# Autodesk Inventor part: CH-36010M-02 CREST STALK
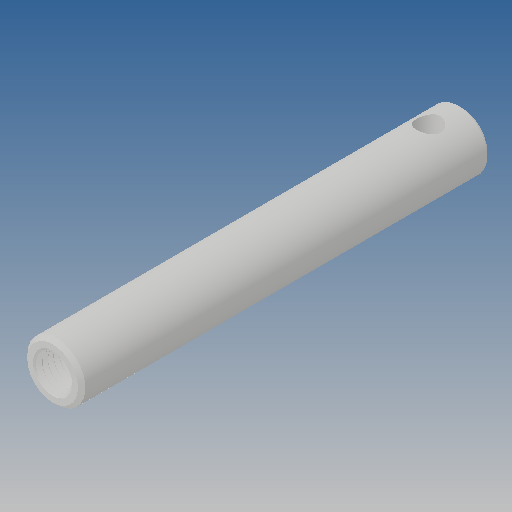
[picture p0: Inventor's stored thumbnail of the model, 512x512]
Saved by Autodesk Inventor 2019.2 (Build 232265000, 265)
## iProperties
Created: 2012-09
Part Number: CH-36010M-02 CREST STALK
Material: Ogólny
Document SubType Name: Modeling
Designer: CADENGINEERING4
Density: 1 g/cm^3
Appearance: Domyślna
Author: CADENGINEERING4
Revision Number: ÈÎºÎ
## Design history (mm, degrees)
feature "ÇÐ³ý-É¨Ãè1"
node "Bryła1"
